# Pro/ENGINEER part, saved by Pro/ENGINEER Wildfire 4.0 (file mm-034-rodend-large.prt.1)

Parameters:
  METRIC = "NO"

Other parameters: PITCH, DRILL_POINT_ANGLE, DRILL_DEPTH, DRILL_DIAMETER, THREAD_DIAMETER, THREADS_PER_INCH, THREAD_DEPTH, THREAD_LENGTH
